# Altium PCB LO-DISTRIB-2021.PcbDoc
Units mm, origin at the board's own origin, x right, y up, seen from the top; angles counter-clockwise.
Board outline 118.3 x 92.9 mm, 2 copper layers (TopLayer, BottomLayer), stack 1.535 mm thick; 58 components, 37 nets, 177 pads, 973 vias.
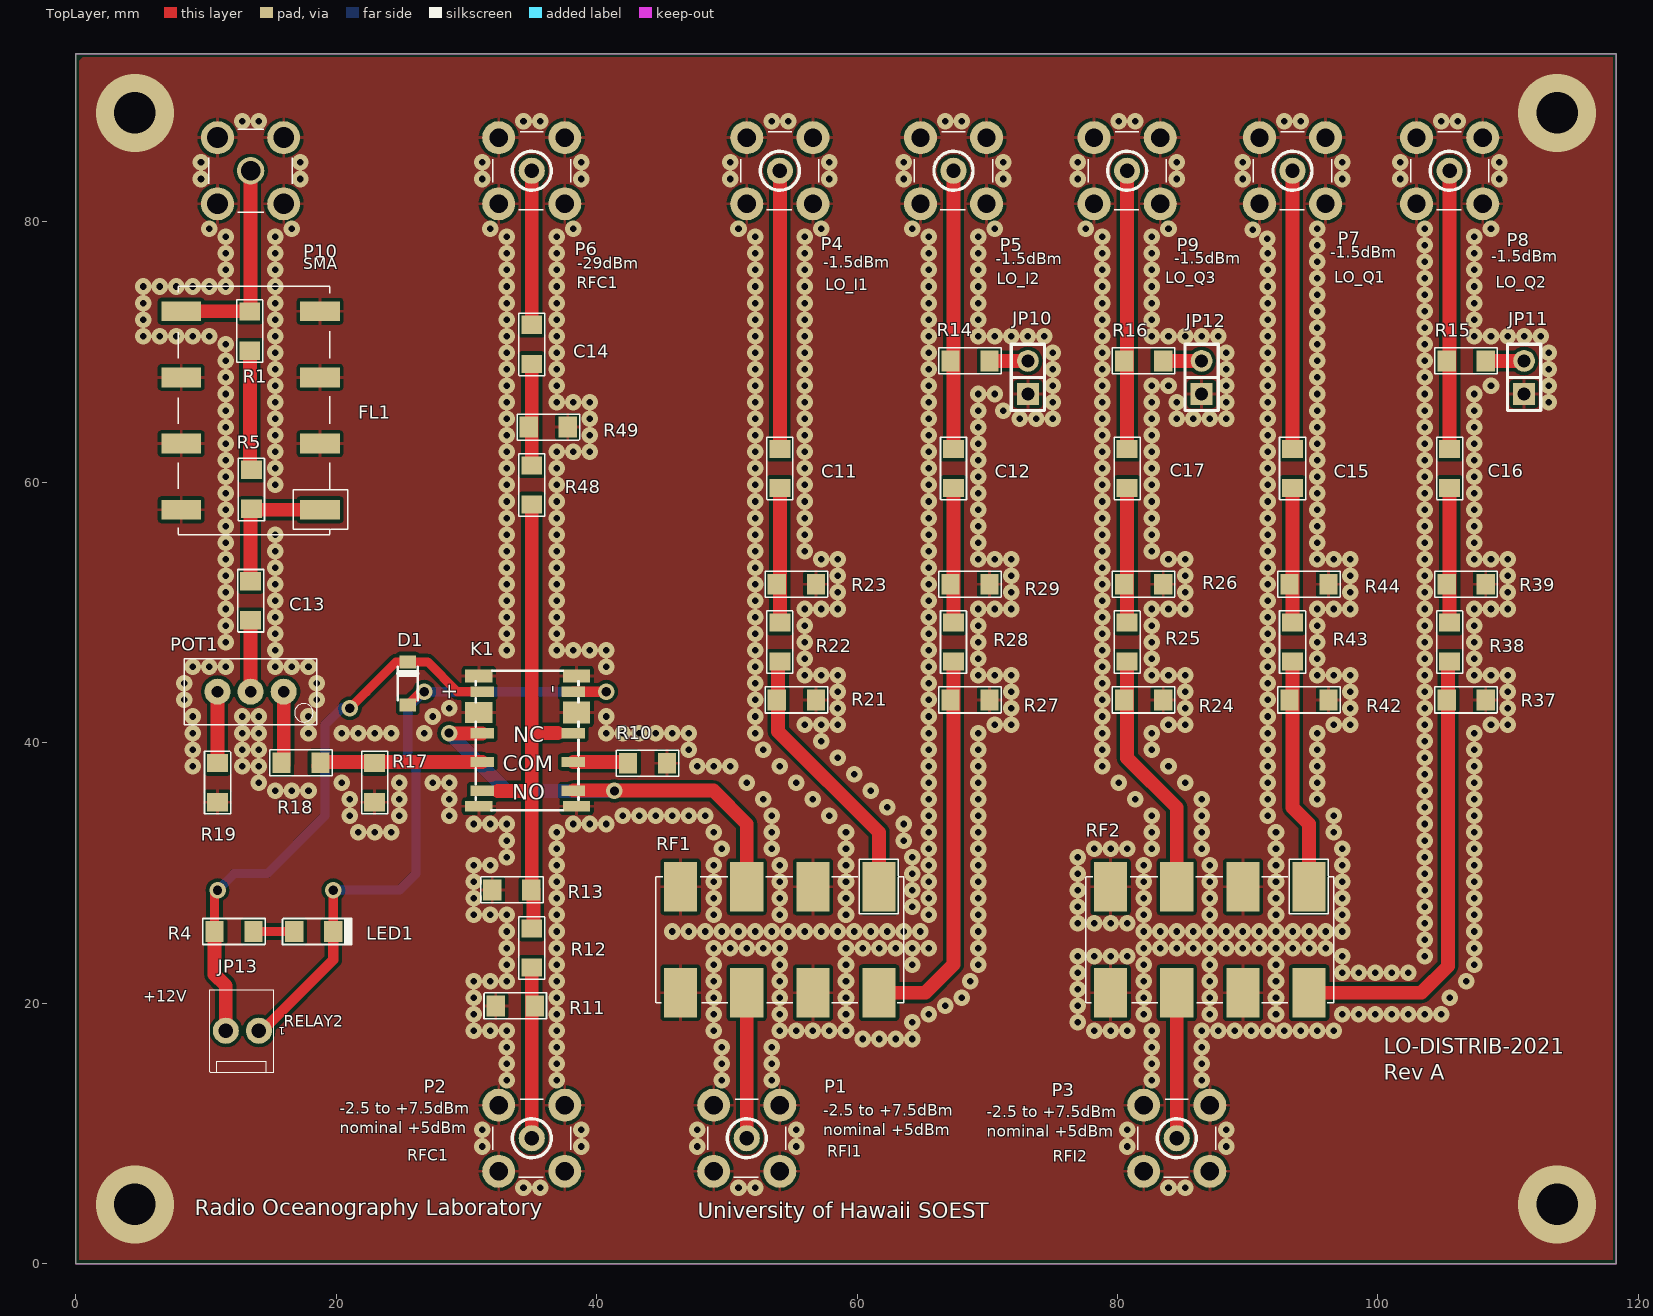
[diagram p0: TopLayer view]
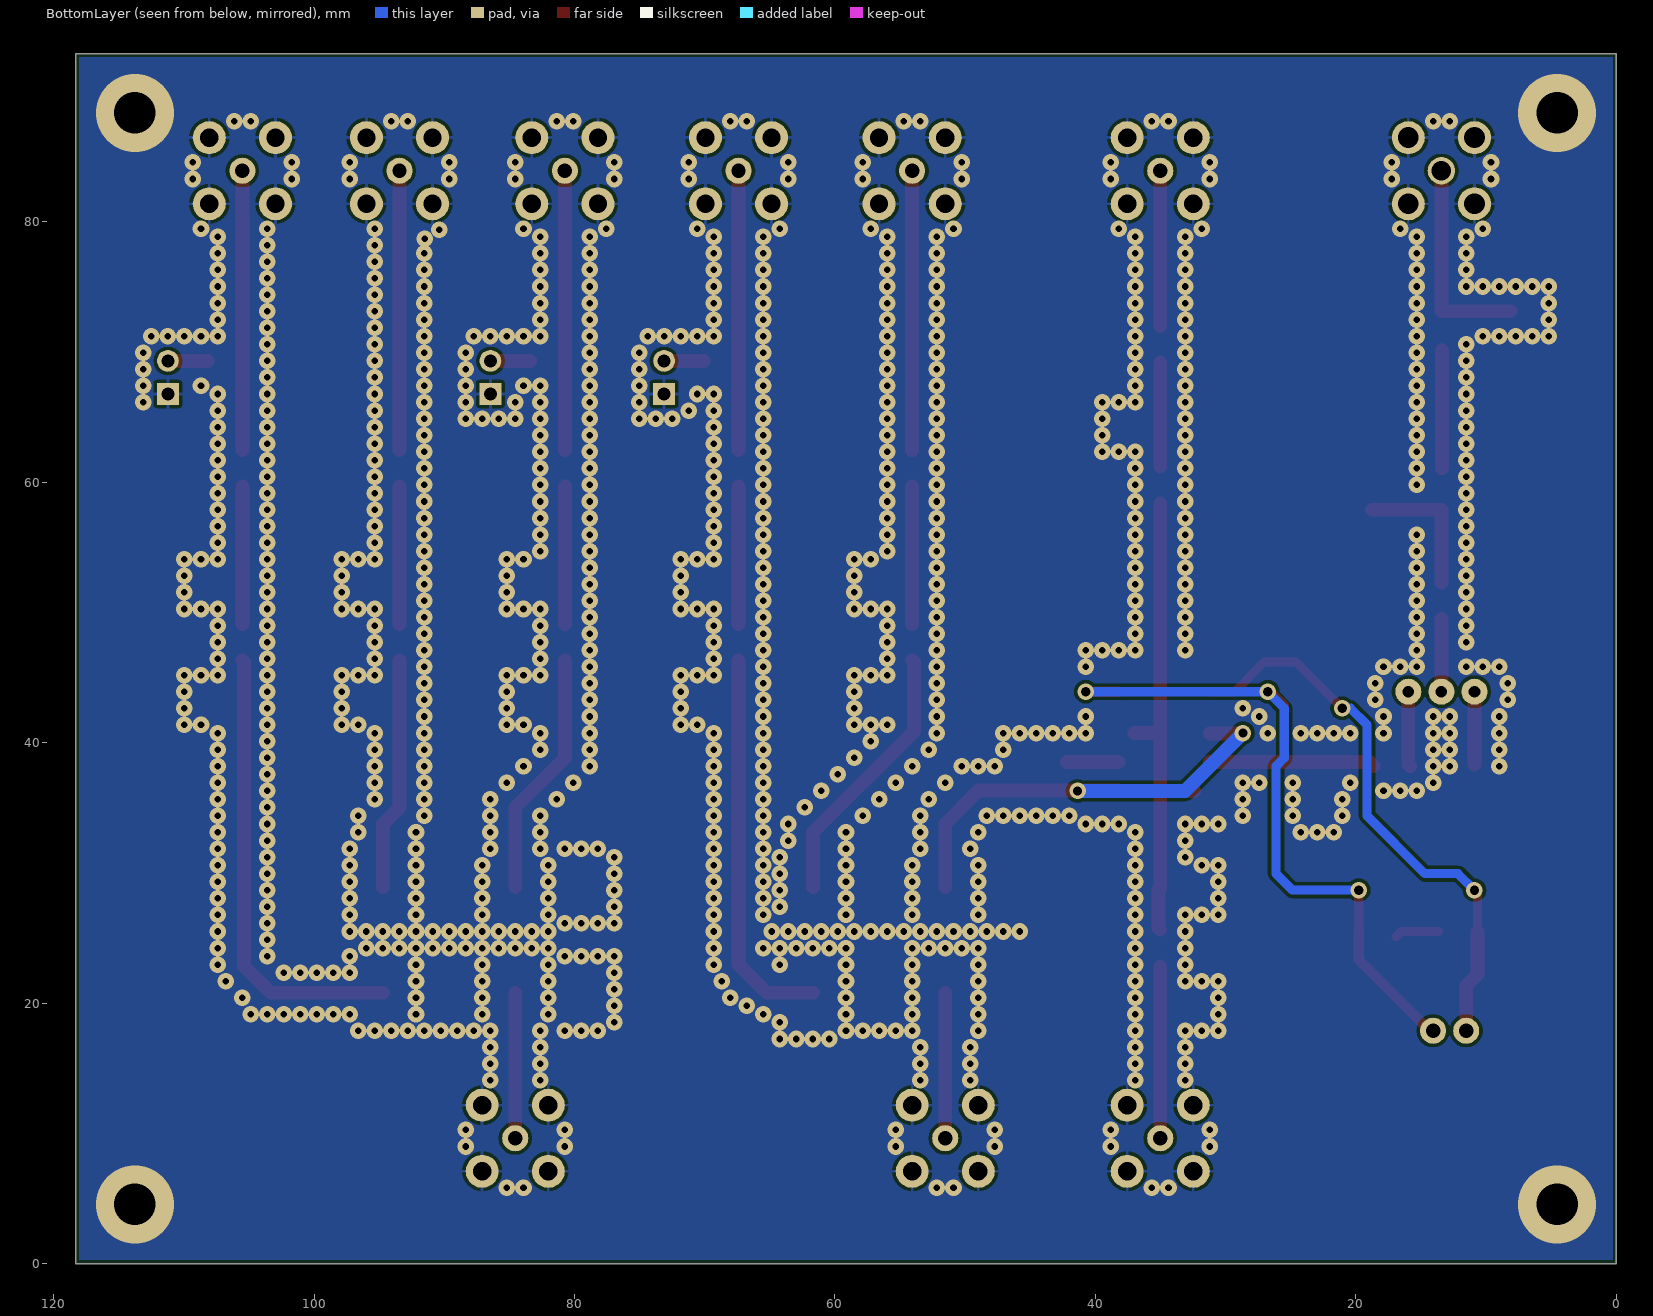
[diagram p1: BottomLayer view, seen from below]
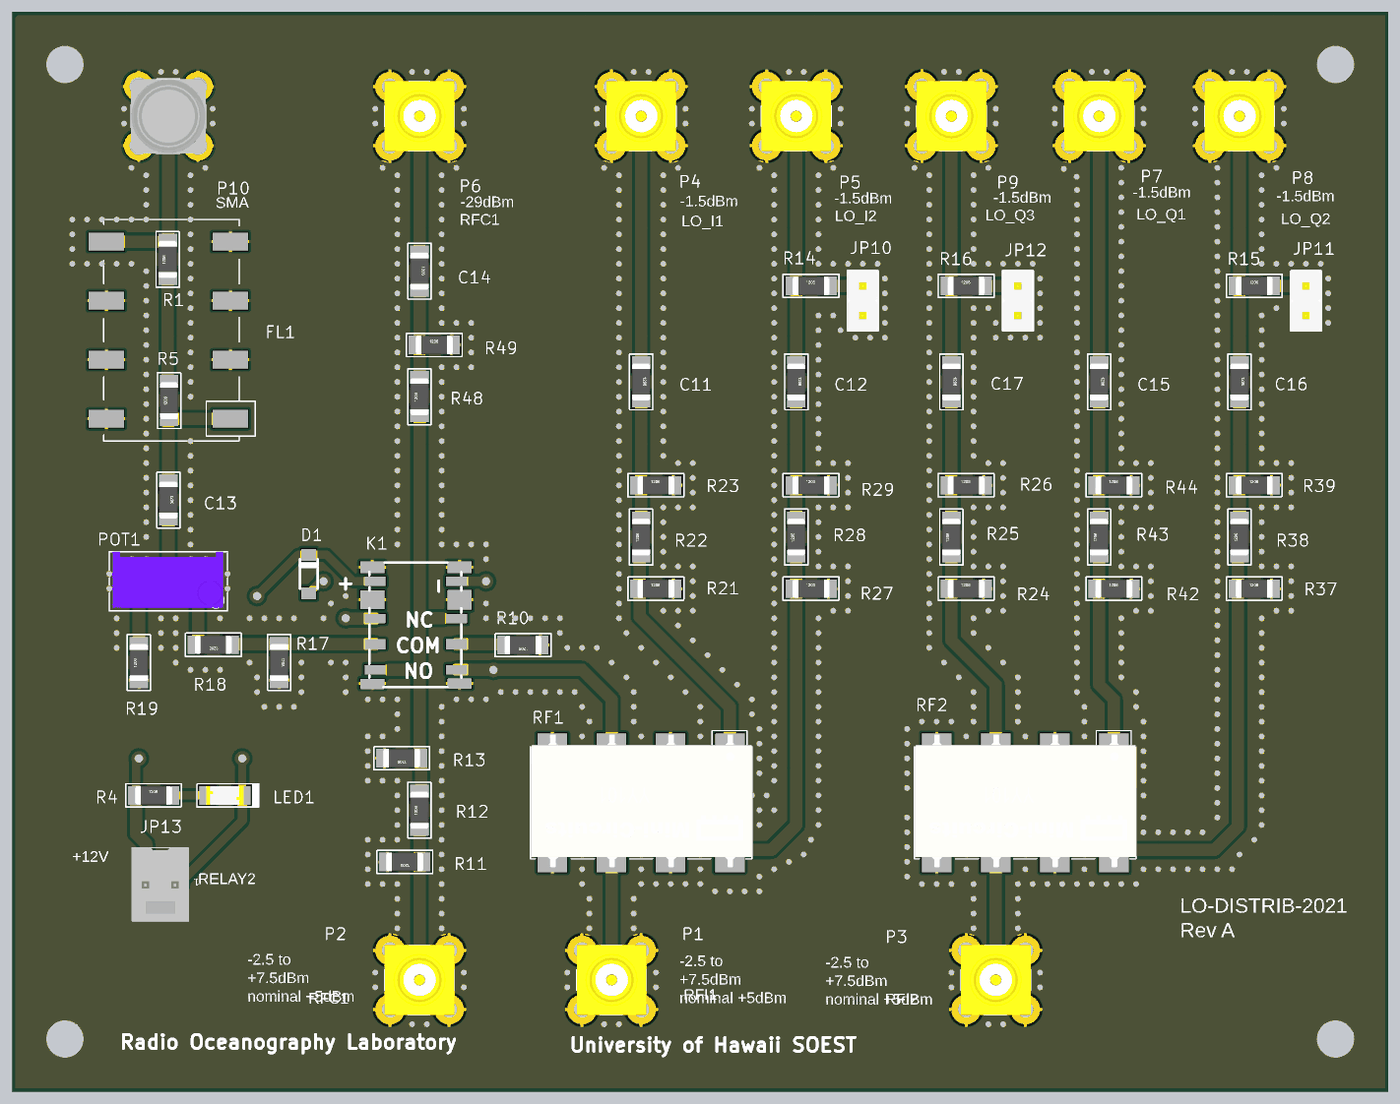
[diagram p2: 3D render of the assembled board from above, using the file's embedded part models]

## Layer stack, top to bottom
TopSolder: solder mask 0.02, Solder Resist, Dk 4
TopLayer: signal copper 0.035
Dielectric1: dielectric 1.465, FR-4, Dk 4.74
BottomLayer: signal copper 0.035
BottomSolder: solder mask 0.02, Solder Resist, Dk 4

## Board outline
0,0 118.3,0 118.3,92.9 0,92.9

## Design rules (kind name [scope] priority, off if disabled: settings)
Clearance Clearance_2 [InNetClass('50R')] p1: gap=0.257 ignorepadtopadclearanceinfootprint=FALSE except(0: Arc-Hole Track-Hole SMDPad-Hole THPad-Hole Via-Hole Fill-Hole Poly-Hole Region-Hole Text-Hole)
Clearance Clearance_1 [OnLayer('Keep-Out Layer')] p2 off: gap=0.5 ignorepadtopadclearanceinfootprint=FALSE except(0: Arc-Hole Track-Hole SMDPad-Hole THPad-Hole Via-Hole Fill-Hole Poly-Hole Region-Hole Text-Hole)
Clearance [All] p3: gap=0.257 ignorepadtopadclearanceinfootprint=FALSE except(0: Arc-Hole Track-Hole SMDPad-Hole THPad-Hole Via-Hole Fill-Hole Poly-Hole Region-Hole Text-Hole)
HoleSize [All] p1: absolutevalues=TRUE maxlimit=10 minlimit=0.025 maxpercent=80.000 minpercent=20.000
MinimumSolderMaskSliver [All] p1 off: minsoldermaskwidth=0.254
PolygonConnect [All] p1: thpad.connectstyle=Relief thpad.reliefconductorwidth=0.254 thpad.reliefentries=4 thpad.polygonreliefangle="90 Angle" thpad.airgapwidth=0.254 smdpad.connectstyle=Relief smdpad.reliefconductorwidth=0.254 smdpad.reliefentries=4 smdpad.polygonreliefangle="90 Angle" smdpad.airgapwidth=0.254 via.connectstyle=Direct via.reliefconductorwidth=0.254 via.reliefentries=4 via.polygonreliefangle="45 Angle" via.airgapwidth=0.254
RoutingVias [All] p1: holewidth=0.711 width=1.27 viastyle="Through Hole" minholewidth=0.5 minwidth=1.27 maxholewidth=0.711 maxwidth=1.27
SilkToSilkClearance [All] p1 off: silktosilkclearance=0.254
SilkToSolderMaskClearance [IsPad] p1 off: minsilkscreentomaskgap=0.254 clearancetoexposedcopper=TRUE
SolderMaskExpansion [All] p1: expansion=0.102
Width Width_1 [InNetClass('50R')] p1: maxlimit=1.064 minlimit=1.064 preferedwidth=1.064 minimp=50.000000 maximp=50.000000 favimp=50.000000
Width [All] p2: maxlimit=1.064 minlimit=0.7 preferedwidth=1.064 minimp=50.000000 maximp=50.000000 favimp=50.000000
26 further rules are at their usual default settings.

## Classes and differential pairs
net class 50R: LOI3 NetC11_1 NetC11_2 NetC12_1 NetC12_2 NetC13_1 NetC13_2 NetC14_1 NetC14_2 NetC15_1 NetC15_2 NetC16_1 NetC16_2 NetC17_1 NetC17_2 NetFL1_8 NetJP10_2 NetJP11_2 NetJP12_2 NetK1_3 NetK1_4 NetK1_6 NetR1_1 NetR21_1 NetR24_1 NetR27_1 NetR37_1 NetR42_1 RFC1 RFI1 RFQ

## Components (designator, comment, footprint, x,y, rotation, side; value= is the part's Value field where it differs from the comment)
C11 "22nF" 1206 54.07,61.055 r270 top
C12 "22nF" 1206 67.405,61.055 r270 top
C13 "22nF" 1206 13.43,50.895 r270 top
C14 "22nF" 1206 35.02,70.58 r270 top
C15 "22nF" 1206 93.44,61.055 r270 top
C16 "22nF" 1206 105.505,61.055 r270 top
C17 "22nF" 1206 80.74,61.055 r270 top
D1 "BAT-48" SOD123 25.495,44.545 r90 top
FL1 "SXLP-ff" HF1149 13.43,65.5 r90 top
JP10 "" 2X2.54 73.12,66.77 r180 top
JP11 "" 2X2.54 111.22,66.77 r180 top
JP12 "" 2X2.54 86.455,66.77 r180 top
JP13 "" 22112022 14.065,17.875 r180 top
K1 "G6K-2F-RF-S DC12" RELAY-RF 31.21,43.91 r270 top
LED1 "CAL" LED1206-BLEUE 19.78,25.495 r180 top
P1 "RF-I" MCX-J-P-H-ST-TH1 51.53,9.62 r0 top
P2 "RF-CAL" MCX-J-P-H-ST-TH1 35.02,9.62 r0 top
P3 "RF-Q" MCX-J-P-H-ST-TH1 84.55,9.62 r0 top
P4 "LO-I1" MCX-J-P-H-ST-TH1 54.07,83.915 r0 top
P5 "LO-I2" MCX-J-P-H-ST-TH1 67.405,83.915 r0 top
P6 "RF CAL" MCX-J-P-H-ST-TH1 35.02,83.915 r0 top
P7 "LO-Q1" MCX-J-P-H-ST-TH1 93.44,83.915 r0 top
P8 "LO-Q2" MCX-J-P-H-ST-TH1 105.505,83.915 r0 top
P9 "LO-Q3" MCX-J-P-H-ST-TH1 80.74,83.915 r0 top
P10 "" 5-1814832-1 13.43,83.915 r90 top
POT1 "100 POT" 3296W 10.89,43.91 r90 top
R1 "ZEROHM" 1206 13.369,71.599 r90 top
R4 "4.99K" 1206 12.16,25.495 r0 top
R5 "ZEROHM" 1206 13.495,59.451 r90 top
R10 "49.9" 1206 43.914,38.419 r180 top
R11 "178" 1206 33.75,19.78 r180 top
R12 "31.6" 1206 35.02,24.225 r90 top
R13 "178" 1206 33.489,28.692 r180 top
R14 "49.9k" 1206 68.675,69.31 r0 top
R15 "49.9k" 1206 106.775,69.31 r0 top
R16 "49.9k" 1206 82.01,69.31 r0 top
R17 "750" 1206 22.955,36.925 r270 top
R18 "10R" 1206 17.297,38.451 r180 top
R19 "49.9" 1206 10.89,36.925 r90 top
R21 "576" 1206 55.34,43.275 r0 top
R22 "8.66" 1206 54.07,47.72 r90 top
R23 "576" 1206 55.34,52.165 r0 top
R24 "576" 1206 82.01,43.275 r0 top
R25 "8.66" 1206 80.74,47.72 r90 top
R26 "576" 1206 82.01,52.165 r0 top
R27 "576" 1206 68.675,43.275 r0 top
R28 "8.66" 1206 67.405,47.72 r90 top
R29 "576" 1206 68.675,52.165 r0 top
R37 "576" 1206 106.775,43.275 r0 top
R38 "8.66" 1206 105.505,47.72 r90 top
R39 "576" 1206 106.775,52.165 r0 top
R42 "576" 1206 94.71,43.275 r0 top
R43 "8.66" 1206 93.44,47.72 r90 top
R44 "576" 1206 94.71,52.165 r0 top
R48 "9.53K" 1206 35.02,59.785 r90 top
R49 "49.9" 1206 36.29,64.23 r0 top
RF1 "SCP-3-1" SCP-3-1 54.07,24.86 r180 top
RF2 "SCP-3-1" SCP-3-1 87.09,24.86 r180 top

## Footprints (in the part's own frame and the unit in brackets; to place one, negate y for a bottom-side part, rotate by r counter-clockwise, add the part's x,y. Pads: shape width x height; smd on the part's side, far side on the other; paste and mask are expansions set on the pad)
2X2.54 [mm]
  rect 1.67x1.67 hole 1: 1(0,0)
  round 1.67 hole 1: 2(0,-2.54)
  silkscreen extent -1.27,-3.81 1.27,1.27, body extent -1.26,-3.8 1.28,1.28, height 9.54
5-1814832-1 [mm]
  round 2.1 hole 1.5: 1(0,0)
  round 2.54 hole 1.6: 2(-2.54,2.54) 5(-2.54,-2.54)
  round 2.54 hole 1.6 mask+0.1: 3(2.54,2.54) 4(2.54,-2.54)
  silkscreen extent -3.2,-3.2 3.2,3.2, body extent -3.2,-3.2 3.2,3.2, height 9.5
1206 [mm]
  rect 1.4x1.6 smd mask+0.05: 1(-1.5,0) 2(1.5,0)
  silkscreen extent -2.4,-1 2.4,1, body extent -1.6,-0.8 1.6,0.8, height 1
3296W [mm]
  round 2 hole 0.9 mask+0.1: 1(0,0) 2(0,-2.54) 3(0,-5.08)
  silkscreen extent -2.54,-7.62 2.54,2.54, body extent -2.28,-7.29 2.55,2.26, height 11.6
22112022 [mm]
  round 2 hole 1.1 mask+0.1: 1(0,0) 2(2.54,0)
  silkscreen extent -1.14,-3.14 3.78,3.19, body extent -1.13,-3.16 3.79,3.19, height 10.68
HF1149 [mil]
  rect 60x120 smd mask+3.94: 1(-300,-209.84) 2(-300,209.84) 3(-100,-209.84) 4(-100,209.84) 5(100,-209.84) 6(100,209.84) 7(300,-209.84) 8(300,209.84)
  silkscreen extent -375,-294 375,219
LED1206-BLEUE [mm]
  rect 1.4x1.6 smd: A(3,0) K(0,0)
  silkscreen extent -1.41,-1 3.9,1, body extent -0.1,-0.84 3.1,0.82, height 1.8
MCX-J-P-H-ST-TH1 [mm]
  round 2 hole 1.1 mask+0.2: 1(0,0)
  round 2.54 hole 1.4 mask+0.2: 2(-2.54,2.54) 3(-2.54,-2.54) 4(2.54,2.54) 5(2.54,-2.54)
  silkscreen extent -3,-3 3,3, body extent -3,-3 3,3, height 5.81
RELAY-RF [mm]
  rect 0.8x1.8 smd: 1(0,0) 2(3.2,0) 3(5.4,0) 4(7.6,0) 5(7.6,7) 6(5.4,7) 7(3.2,7) 8(0,7)
  rect 1x2.1 smd: 10(-1.2,-0.25) 15(-1.2,7.25)
  rect 1.6x2.1 smd: 11(1.6,-0.25)
  rect 0.8x2.1 smd: 12(8.8,-0.25) 13(8.8,7.25)
  rect 1.7x2.1 smd: 14(1.6,7.25)
  silkscreen extent -1.6,-0.5 9.1,7.4
SCP-3-1 [mm]
  rect 2.54x3.81 smd mask+0.1: 1(-7.62,-4.065) 2(-7.62,4.065) 3(-2.54,-4.065) 4(-2.54,4.065) 5(2.54,-4.065) 6(2.54,4.065) 7(7.62,-4.065) 8(7.62,4.065)
  silkscreen extent -9.53,-6.2 9.53,4.82, body extent -9.56,-5.87 9.49,5.56, height 5.34
SOD123 [mil]
  rect 40x50 smd: A(-65,0) K(65,0)
  silkscreen extent -50,-30 50,30

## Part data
C11 C12 C14 C15 C16 C17: library part CAP1206
C13: library part CAP
D1: library part "DIODE SCHOTTKY"
FL1: library part "LP FILTER_1"
JP10 JP11 JP12 JP13: library part STRAP
K1: library part "RELAY DPDT_1"
LED1: library part LED_1
P1 P2 P3: library part MCX_PCB, "MCX-J-P-H-ST-TH1"
P4 P5 P6 P7 P8 P9: library part MCX_PCB
P10: library part SMA-4G
POT1: library part POT
R1 R4 R5 R10 R17 R18 R19 R48 R49: library part RES1206
R11 R12 R13 R14 R15 R16 R21 R22 R23 R24 R25 R26 R27 R28 R29 R37 R38 R39 R42 R43 R44: library part RES

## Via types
v1: diameter 1.27, hole 0.5, TopLayer to BottomLayer, 962 vias
v2: diameter 1.27, hole 0.711, TopLayer to BottomLayer, 7 vias
v3: diameter 6, hole 3.2, TopLayer to BottomLayer, 4 vias

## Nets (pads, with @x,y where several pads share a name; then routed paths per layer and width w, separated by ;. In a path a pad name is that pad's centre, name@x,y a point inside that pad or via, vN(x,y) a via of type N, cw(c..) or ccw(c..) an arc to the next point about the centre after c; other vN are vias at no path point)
+12V: D1.K JP13.2 K1.1 R4.1 | length 43.9
  TopLayer w0.7: R4.1 10.66,28.44 v2(10.89,28.67) ; v2(21.05,42.64) 22.32,43.91 24.606,46.196 D1.K 27.019,46.196 29.305,43.91 K1.1
  TopLayer w1.064: R4.1 10.66,22.194 11.525,21.329 JP13.2
  BottomLayer w0.7: v2(10.89,28.67) 12.16,29.94 14.7,29.94 19.145,34.385 19.145,41.37 20.415,42.64 v2(21.05,42.64)
GND: FL1.2 FL1.3 FL1.4 FL1.5 FL1.6 FL1.7 JP10.1 JP11.1 JP12.1 K1.10 K1.11 K1.12 K1.13 K1.14 K1.15 P1.2 P1.3 P1.4 P1.5 P2.2 P2.3 P2.4 P2.5 P3.2 P3.3 P3.4 P3.5 P4.2 P4.3 P4.4 P4.5 P5.2 P5.3 P5.4 P5.5 P6.2 P6.3 P6.4 P6.5 P7.2 P7.3 P7.4 P7.5 P8.2 P8.3 P8.4 P8.5 P9.2 P9.3 P9.4 P9.5 P10.2 P10.3 P10.4 P10.5 R10.1 R11.2 R13.2 R17.2 R19.1 R21.2 R23.2 R24.2 R26.2 R27.2 R29.2 R37.2 R39.2 R42.2 R44.2 R49.2 RF1.3 RF1.4 RF1.7 RF1.8 RF2.3 RF2.4 RF2.7 RF2.8
  other v1: 34.385,5.81 35.655,5.81 50.895,5.81 52.165,5.81 83.915,5.81 85.185,5.81 31.21,8.985 38.83,8.985 47.72,8.985 55.34,8.985 80.74,8.985 88.36,8.985 31.21,10.255 38.83,10.255 47.72,10.255 55.34,10.255 80.74,10.255 88.36,10.255 33.115,14.065 36.925,14.065 49.625,14.065 53.435,14.065 82.645,14.065 86.455,14.065 33.115,15.335 36.925,15.335 49.625,15.335 53.435,15.335 82.645,15.335 86.455,15.335 33.115,16.605 36.925,16.605 49.625,16.605 53.435,16.605 82.645,16.605 86.455,16.605 60.42,17.24 61.69,17.24 62.96,17.24 64.23,17.24 30.575,17.875 31.845,17.875 33.115,17.875 36.925,17.875 48.99,17.875 54.07,17.875 55.34,17.875 56.61,17.875 57.88,17.875 59.15,17.875 78.2,17.875 79.47,17.875 80.74,17.875 82.645,17.875 86.455,17.875 87.725,17.875 88.995,17.875 90.265,17.875 91.535,17.875 92.805,17.875 94.075,17.875 95.345,17.875 96.615,17.875 64.23,18.51 76.93,18.51 30.575,19.145 36.925,19.145 48.99,19.145 54.07,19.145 59.15,19.145 65.5,19.145 82.01,19.145 87.09,19.145 92.17,19.145 97.25,19.145 98.52,19.145 99.79,19.145 101.06,19.145 102.33,19.145 103.6,19.145 104.87,19.145 66.77,19.78 76.93,19.78 30.575,20.415 36.925,20.415 48.99,20.415 54.07,20.415 59.15,20.415 68.04,20.415 82.01,20.415 87.09,20.415 92.17,20.415 105.505,20.415 76.93,21.05 30.575,21.685 31.845,21.685 33.115,21.685 36.925,21.685 48.99,21.685 54.07,21.685 59.15,21.685 68.675,21.685 82.01,21.685 87.09,21.685 92.17,21.685 106.775,21.685 76.93,22.32 97.25,22.32 98.52,22.32 99.79,22.32 101.06,22.32 102.33,22.32 33.115,22.955 36.925,22.955 48.99,22.955 54.07,22.955 59.15,22.955 64.23,22.955 69.31,22.955 82.01,22.955 87.09,22.955 92.17,22.955 107.41,22.955 76.93,23.59 78.2,23.59 79.47,23.59 80.74,23.59 97.25,23.59 103.6,23.59 33.115,24.225 36.925,24.225 48.99,24.225 50.26,24.225 51.53,24.225 52.8,24.225 54.07,24.225 59.15,24.225 60.42,24.225 61.69,24.225 62.96,24.225 64.23,24.225 65.5,24.225 69.31,24.225 82.01,24.225 83.28,24.225 84.55,24.225 85.82,24.225 87.09,24.225 88.36,24.225 89.63,24.225 90.9,24.225 92.17,24.225 93.44,24.225 94.71,24.225 95.98,24.225 107.41,24.225 103.6,24.86 33.115,25.495 36.925,25.495 45.815,25.495 47.085,25.495 48.355,25.495 49.625,25.495 50.895,25.495 52.165,25.495 53.435,25.495 54.705,25.495 55.975,25.495 57.245,25.495 58.515,25.495 59.785,25.495 61.055,25.495 62.325,25.495 63.595,25.495 64.865,25.495 69.31,25.495 82.01,25.495 83.28,25.495 84.55,25.495 85.82,25.495 87.09,25.495 88.36,25.495 89.63,25.495 90.9,25.495 92.17,25.495 93.44,25.495 94.71,25.495 95.98,25.495 97.25,25.495 107.41,25.495 76.93,26.13 78.2,26.13 79.47,26.13 80.74,26.13 103.6,26.13 30.575,26.765 31.845,26.765 33.115,26.765 36.925,26.765 48.99,26.765 54.07,26.765 59.15,26.765 65.5,26.765 69.31,26.765 82.01,26.765 87.09,26.765 92.17,26.765 97.25,26.765 107.41,26.765 64.23,27.4 76.93,27.4 103.6,27.4 30.575,28.035 36.925,28.035 48.99,28.035 54.07,28.035 59.15,28.035 65.5,28.035 69.31,28.035 82.01,28.035 87.09,28.035 92.17,28.035 97.25,28.035 107.41,28.035 64.23,28.67 76.93,28.67 103.6,28.67 30.575,29.305 36.925,29.305 48.99,29.305 54.07,29.305 59.15,29.305 65.5,29.305 69.31,29.305 82.01,29.305 87.09,29.305 92.17,29.305 97.25,29.305 107.41,29.305 64.23,29.94 76.93,29.94 103.6,29.94 30.575,30.575 31.845,30.575 36.925,30.575 48.99,30.575 54.07,30.575 59.15,30.575 65.5,30.575 69.31,30.575 82.01,30.575 87.09,30.575 92.17,30.575 97.25,30.575 107.41,30.575 33.115,31.21 64.23,31.21 76.93,31.21 103.6,31.21 36.925,31.845 49.625,31.845 53.435,31.845 59.15,31.845 65.5,31.845 69.31,31.845 78.2,31.845 79.47,31.845 80.74,31.845 82.645,31.845 86.455,31.845 92.17,31.845 97.25,31.845 107.41,31.845 33.115,32.48 63.595,32.48 103.6,32.48 21.685,33.115 22.955,33.115 24.225,33.115 36.925,33.115 48.99,33.115 53.435,33.115 59.15,33.115 65.5,33.115 69.31,33.115 82.645,33.115 86.455,33.115 92.17,33.115 96.615,33.115 107.41,33.115 30.575,33.75 31.845,33.75 33.115,33.75 38.195,33.75 39.465,33.75 40.735,33.75 63.595,33.75 103.6,33.75 21.05,34.385 24.86,34.385 28.67,34.385 42.005,34.385 43.275,34.385 44.545,34.385 45.815,34.385 47.085,34.385 48.355,34.385 53.435,34.385 57.88,34.385 65.5,34.385 69.31,34.385 82.645,34.385 86.455,34.385 91.535,34.385 96.615,34.385 107.41,34.385 62.325,35.02 103.6,35.02 21.05,35.655 24.86,35.655 28.67,35.655 52.8,35.655 56.61,35.655 65.5,35.655 69.31,35.655 81.375,35.655 86.455,35.655 91.535,35.655 95.345,35.655 107.41,35.655 15.335,36.29 16.605,36.29 17.875,36.29 61.055,36.29 103.6,36.29 14.065,36.925 20.415,36.925 24.86,36.925 27.4,36.925 28.67,36.925 51.53,36.925 55.34,36.925 65.5,36.925 69.31,36.925 80.105,36.925 85.185,36.925 91.535,36.925 95.345,36.925 107.41,36.925 59.785,37.56 103.6,37.56 8.985,38.195 12.795,38.195 14.065,38.195 47.72,38.195 48.99,38.195 50.26,38.195 54.07,38.195 65.5,38.195 69.31,38.195 78.835,38.195 83.915,38.195 91.535,38.195 95.345,38.195 107.41,38.195 58.515,38.83 103.6,38.83 8.985,39.465 12.795,39.465 14.065,39.465 47.085,39.465 52.8,39.465 65.5,39.465 69.31,39.465 78.835,39.465 82.645,39.465 91.535,39.465 95.345,39.465 107.41,39.465 57.245,40.1 103.6,40.1 8.985,40.735 12.795,40.735 14.065,40.735 17.875,40.735 20.415,40.735 21.685,40.735 22.955,40.735 24.225,40.735 26.765,40.735 40.735,40.735 42.005,40.735 43.275,40.735 44.545,40.735 45.815,40.735 47.085,40.735 52.165,40.735 65.5,40.735 69.31,40.735 78.835,40.735 82.645,40.735 91.535,40.735 95.345,40.735 107.41,40.735 55.975,41.37 57.245,41.37 58.515,41.37 70.58,41.37 71.85,41.37 83.915,41.37 85.185,41.37 96.615,41.37 97.885,41.37 103.6,41.37 108.68,41.37 109.95,41.37 8.985,42.005 12.795,42.005 14.065,42.005 17.875,42.005 27.4,42.005 40.735,42.005 52.165,42.005 65.5,42.005 78.835,42.005 91.535,42.005 28.67,42.64 58.515,42.64 71.85,42.64 85.185,42.64 97.885,42.64 103.6,42.64 109.95,42.64 8.35,43.275 18.51,43.275 52.165,43.275 65.5,43.275 78.835,43.275 91.535,43.275 58.515,43.91 71.85,43.91 85.185,43.91 97.885,43.91 103.6,43.91 109.95,43.91 8.35,44.545 18.51,44.545 52.165,44.545 65.5,44.545 78.835,44.545 91.535,44.545 55.975,45.18 57.245,45.18 58.515,45.18 69.31,45.18 70.58,45.18 71.85,45.18 82.645,45.18 83.915,45.18 85.185,45.18 95.345,45.18 96.615,45.18 97.885,45.18 103.6,45.18 107.41,45.18 108.68,45.18 109.95,45.18 8.985,45.815 10.255,45.815 11.525,45.815 15.335,45.815 16.605,45.815 17.875,45.815 40.735,45.815 52.165,45.815 65.5,45.815 78.835,45.815 91.535,45.815 55.975,46.45 69.31,46.45 82.645,46.45 95.345,46.45 103.6,46.45 107.41,46.45 15.335,47.085 33.115,47.085 36.925,47.085 38.195,47.085 39.465,47.085 40.735,47.085 52.165,47.085 65.5,47.085 78.835,47.085 91.535,47.085 11.525,47.72 55.975,47.72 69.31,47.72 82.645,47.72 95.345,47.72 103.6,47.72 107.41,47.72 15.335,48.355 33.115,48.355 36.925,48.355 52.165,48.355 65.5,48.355 78.835,48.355 91.535,48.355 11.525,48.99 55.975,48.99 69.31,48.99 82.645,48.99 95.345,48.99 103.6,48.99 107.41,48.99 15.335,49.625 33.115,49.625 36.925,49.625 52.165,49.625 65.5,49.625 78.835,49.625 91.535,49.625 11.525,50.26 55.975,50.26 57.245,50.26 58.515,50.26 69.31,50.26 70.58,50.26 71.85,50.26 82.645,50.26 83.915,50.26 85.185,50.26 95.345,50.26 96.615,50.26 97.885,50.26 103.6,50.26 107.41,50.26 108.68,50.26 109.95,50.26 15.335,50.895 33.115,50.895 36.925,50.895 52.165,50.895 65.5,50.895 78.835,50.895 91.535,50.895 11.525,51.53 58.515,51.53 71.85,51.53 85.185,51.53 97.885,51.53 103.6,51.53 109.95,51.53 15.335,52.165 33.115,52.165 36.925,52.165 52.165,52.165 65.5,52.165 78.835,52.165 91.535,52.165 11.525,52.8 58.515,52.8 71.85,52.8 85.185,52.8 97.885,52.8 103.6,52.8 109.95,52.8 15.335,53.435 33.115,53.435 36.925,53.435 52.165,53.435 65.5,53.435 78.835,53.435 91.535,53.435 11.525,54.07 57.245,54.07 58.515,54.07 69.31,54.07 70.58,54.07 71.85,54.07 83.915,54.07 85.185,54.07 95.345,54.07 96.615,54.07 97.885,54.07 103.6,54.07 107.41,54.07 108.68,54.07 109.95,54.07 15.335,54.705 33.115,54.705 36.925,54.705 52.165,54.705 55.975,54.705 65.5,54.705 78.835,54.705 82.645,54.705 91.535,54.705 11.525,55.34 69.31,55.34 95.345,55.34 103.6,55.34 107.41,55.34 15.335,55.975 33.115,55.975 36.925,55.975 52.165,55.975 55.975,55.975 65.5,55.975 78.835,55.975 82.645,55.975 91.535,55.975 11.525,56.61 69.31,56.61 95.345,56.61 103.6,56.61 107.41,56.61 33.115,57.245 36.925,57.245 52.165,57.245 55.975,57.245 65.5,57.245 78.835,57.245 82.645,57.245 91.535,57.245 11.525,57.88 69.31,57.88 95.345,57.88 103.6,57.88 107.41,57.88 33.115,58.515 36.925,58.515 52.165,58.515 55.975,58.515 65.5,58.515 78.835,58.515 82.645,58.515 91.535,58.515 11.525,59.15 69.31,59.15 95.345,59.15 103.6,59.15 107.41,59.15 15.335,59.785 33.115,59.785 36.925,59.785 52.165,59.785 55.975,59.785 65.5,59.785 78.835,59.785 82.645,59.785 91.535,59.785 11.525,60.42 69.31,60.42 95.345,60.42 103.6,60.42 107.41,60.42 15.335,61.055 33.115,61.055 36.925,61.055 52.165,61.055 55.975,61.055 65.5,61.055 78.835,61.055 82.645,61.055 91.535,61.055 11.525,61.69 69.31,61.69 95.345,61.69 103.6,61.69 107.41,61.69 15.335,62.325 33.115,62.325 36.925,62.325 38.195,62.325 39.465,62.325 52.165,62.325 55.975,62.325 65.5,62.325 78.835,62.325 82.645,62.325 91.535,62.325 11.525,62.96 69.31,62.96 95.345,62.96 103.6,62.96 107.41,62.96 15.335,63.595 33.115,63.595 39.465,63.595 52.165,63.595 55.975,63.595 65.5,63.595 78.835,63.595 82.645,63.595 91.535,63.595 11.525,64.23 69.31,64.23 95.345,64.23 103.6,64.23 107.41,64.23 15.335,64.865 33.115,64.865 39.465,64.865 52.165,64.865 55.975,64.865 65.5,64.865 72.485,64.865 73.755,64.865 75.025,64.865 78.835,64.865 82.645,64.865 84.55,64.865 85.82,64.865 87.09,64.865 88.36,64.865 91.535,64.865 11.525,65.5 69.31,65.5 71.215,65.5 95.345,65.5 103.6,65.5 107.41,65.5 15.335,66.135 33.115,66.135 36.925,66.135 38.195,66.135 39.465,66.135 52.165,66.135 55.975,66.135 65.5,66.135 75.025,66.135 78.835,66.135 82.645,66.135 84.55,66.135 88.36,66.135 91.535,66.135 113.125,66.135 11.525,66.77 69.31,66.77 70.58,66.77 95.345,66.77 103.6,66.77 107.41,66.77 15.335,67.405 33.115,67.405 36.925,67.405 52.165,67.405 55.975,67.405 65.5,67.405 75.025,67.405 78.835,67.405 82.645,67.405 83.915,67.405 88.36,67.405 91.535,67.405 108.68,67.405 113.125,67.405 11.525,68.04 95.345,68.04 103.6,68.04 15.335,68.675 33.115,68.675 36.925,68.675 52.165,68.675 55.975,68.675 65.5,68.675 75.025,68.675 78.835,68.675 88.36,68.675 91.535,68.675 113.125,68.675 11.525,69.31 95.345,69.31 103.6,69.31 15.335,69.945 33.115,69.945 36.925,69.945 52.165,69.945 55.975,69.945 65.5,69.945 75.025,69.945 78.835,69.945 88.36,69.945 91.535,69.945 113.125,69.945 11.525,70.58 95.345,70.58 103.6,70.58 5.175,71.215 6.445,71.215 7.715,71.215 8.985,71.215 10.255,71.215 15.335,71.215 33.115,71.215 36.925,71.215 52.165,71.215 55.975,71.215 65.5,71.215 69.31,71.215 70.58,71.215 71.85,71.215 73.12,71.215 74.39,71.215 78.835,71.215 82.645,71.215 83.915,71.215 85.185,71.215 86.455,71.215 87.725,71.215 91.535,71.215 107.41,71.215 108.68,71.215 109.95,71.215 111.22,71.215 112.49,71.215 95.345,71.85 103.6,71.85 5.175,72.485 15.335,72.485 33.115,72.485 36.925,72.485 52.165,72.485 55.975,72.485 65.5,72.485 69.31,72.485 78.835,72.485 82.645,72.485 91.535,72.485 107.41,72.485 95.345,73.12 103.6,73.12 5.175,73.755 15.335,73.755 33.115,73.755 36.925,73.755 52.165,73.755 55.975,73.755 65.5,73.755 69.31,73.755 78.835,73.755 82.645,73.755 91.535,73.755 107.41,73.755 95.345,74.39 103.6,74.39 5.175,75.025 6.445,75.025 7.715,75.025 8.985,75.025 10.255,75.025 11.525,75.025 15.335,75.025 33.115,75.025 36.925,75.025 52.165,75.025 55.975,75.025 65.5,75.025 69.31,75.025 78.835,75.025 82.645,75.025 91.535,75.025 107.41,75.025 95.345,75.66 103.6,75.66 11.525,76.295 15.335,76.295 33.115,76.295 36.925,76.295 52.165,76.295 55.975,76.295 65.5,76.295 69.31,76.295 78.835,76.295 82.645,76.295 91.535,76.295 107.41,76.295 95.345,76.93 103.6,76.93 11.525,77.565 15.335,77.565 33.115,77.565 36.925,77.565 52.165,77.565 55.975,77.565 65.5,77.565 69.31,77.565 78.835,77.565 82.645,77.565 91.535,77.565 107.41,77.565 95.345,78.2 103.6,78.2 91.501,78.704 11.525,78.835 15.335,78.835 33.115,78.835 36.925,78.835 52.165,78.835 55.975,78.835 65.5,78.835 69.31,78.835 78.835,78.835 82.645,78.835 107.41,78.835 90.4,79.377 10.255,79.47 16.605,79.47 31.845,79.47 38.195,79.47 50.895,79.47 57.245,79.47 64.23,79.47 70.58,79.47 77.565,79.47 83.915,79.47 95.345,79.47 103.6,79.47 108.68,79.47 9.62,83.28 17.24,83.28 31.21,83.28 38.83,83.28 50.26,83.28 57.88,83.28 63.595,83.28 71.215,83.28 76.93,83.28 84.55,83.28 89.63,83.28 97.25,83.28 101.695,83.28 109.315,83.28 9.62,84.55 17.24,84.55 31.21,84.55 38.83,84.55 50.26,84.55 57.88,84.55 63.595,84.55 71.215,84.55 76.93,84.55 84.55,84.55 89.63,84.55 97.25,84.55 101.695,84.55 109.315,84.55 12.795,87.725 14.065,87.725 34.385,87.725 35.655,87.725 53.435,87.725 54.705,87.725 66.77,87.725 68.04,87.725 80.105,87.725 81.375,87.725 92.805,87.725 94.075,87.725 104.87,87.725 106.14,87.725
  other v3: 4.54,4.54 113.76,4.54 4.54,88.36 113.76,88.36
LOI3: K1.2 K1.5 RF1.5 | length 36.3
  TopLayer w1.064: v2(28.67,40.735) 28.695,40.71 K1.2 ; K1.5 41.35,36.31 v2(41.37,36.29) ; v2@41.37,36.31 48.97,36.31 51.53,33.75 RF1.5
  BottomLayer w1.064: v2(28.67,40.735) 33.115,36.29 v2(41.37,36.29)
NetC11_1: C11.1 P4.1 | length 21.5
  TopLayer w1.064: C11.1@54.07,62.455 P4.1
NetC11_2: C11.2 R22.2 R23.1 | length 10.5
  TopLayer w1.064: R22.2@54.07,49.12 C11.2@54.07,59.655
NetC12_1: C12.1 P5.1 R14.1 | length 21.5
  TopLayer w1.064: C12.1@67.405,62.455 P5.1
NetC12_2: C12.2 R28.2 R29.1 | length 10.5
  TopLayer w1.064: R28.2@67.405,49.12 C12.2@67.405,59.655
NetC13_1: C13.1 FL1.1 R5.1 | length 10.9
  TopLayer w1.064: C13.1@13.43,52.295 13.43,57.88 FL1.1
NetC13_2: C13.2 POT1.2 | length 5.6
  TopLayer w1.064: POT1.2 C13.2@13.43,49.495
NetC14_1: C14.1 P6.1 | length 11.9
  TopLayer w1.064: C14.1@35.02,71.98 P6.1
NetC14_2: C14.2 R48.2 R49.1 | length 8
  TopLayer w1.064: R48.2@35.02,61.185 C14.2@35.02,69.18
NetC15_1: C15.1 P7.1 | length 21.5
  TopLayer w1.064: C15.1@93.44,62.455 P7.1
NetC15_2: C15.2 R43.2 R44.1 | length 10.5
  TopLayer w1.064: R43.2@93.44,49.12 C15.2@93.44,59.655
NetC16_1: C16.1 P8.1 R15.1 | length 21.5
  TopLayer w1.064: C16.1@105.505,62.455 P8.1
NetC16_2: C16.2 R38.2 R39.1 | length 10.5
  TopLayer w1.064: R38.2@105.505,49.12 C16.2@105.505,59.655
NetC17_1: C17.1 P9.1 R16.1 | length 21.5
  TopLayer w1.064: C17.1@80.74,62.455 P9.1
NetC17_2: C17.2 R25.2 R26.1 | length 10.5
  TopLayer w1.064: R25.2@80.74,49.12 C17.2@80.74,59.655
NetFL1_8: FL1.8 P10.1 R1.2 | length 16.1
  TopLayer w1.064: FL1.8 13.43,73.12 P10.1
NetJP10_2: JP10.2 R14.2 | length 3
  TopLayer w1.064: R14.2@70.075,69.31 JP10.2
NetJP11_2: JP11.2 R15.2 | length 3
  TopLayer w1.064: R15.2@108.175,69.31 JP11.2
NetJP12_2: JP12.2 R16.2 | length 3
  TopLayer w1.064: R16.2@83.41,69.31 JP12.2
NetK1_3: K1.3 R17.1 R18.1 | length 12.7
  TopLayer w1.064: R18.1@18.64,38.195 18.955,38.51 K1.3
NetK1_4: K1.4 K1.7 R12.2 R13.1 R48.1 | length 37.5
  TopLayer w1.064: 32.405,36.29 35.02,36.29 ; R12.2@35.02,25.625 35.15,25.755 35.15,28.67 35.02,28.8 35.02,36.29 ; R48.1@35.02,58.385 35.02,40.735 ; 37.005,40.735 35.02,40.735 ; 35.02,36.29 35.02,40.735
NetK1_6: K1.6 R10.2 | length 4
  TopLayer w1.064: K1.6 R10.2@42.19,38.51
NetLED1_A: LED1.A R4.2 | length 3.4
  TopLayer w0.7: R4.2 16.501,25.495 LED1.A@16.917,25.079
NetPOT1_1: POT1.1 R19.2 | length 5.6
  TopLayer w1.064: R19.2@10.89,38.325 POT1.1
NetPOT1_3: POT1.3 R18.2 | length 5.8
  TopLayer w1.064: R18.2@15.84,38.195 15.97,38.325 POT1.3
NetR1_1: R1.1 R5.2 | length 9
  TopLayer w1.064: R5.2@13.369,61.082 R1.1
NetR21_1: R21.1 R22.1 RF1.1 | length 20.7
  TopLayer w1.064: R22.1@54.07,46.32 53.94,46.19 53.94,43.275 53.94,40.865 61.69,33.115 RF1.1
NetR24_1: R24.1 R25.1 RF2.5 | length 19
  TopLayer w1.064: R25.1@80.74,46.32 80.74,38.83 84.55,35.02 RF2.5
NetR27_1: R27.1 R28.1 RF1.2 | length 30
  TopLayer w1.064: RF1.2 65.245,20.795 67.405,22.955 R28.1@67.405,46.32
NetR37_1: R37.1 R38.1 RF2.2 | length 35.1
  TopLayer w1.064: RF2.2 103.345,20.795 105.375,22.825 105.375,43.275 105.375,46.19 R38.1@105.505,46.32
NetR42_1: R42.1 R43.1 RF2.1 | length 17.9
  TopLayer w1.064: R43.1@93.44,46.32 93.44,35.02 94.71,33.75 RF2.1
RELAY2: D1.A JP13.1 K1.8 LED1.K | length 53
  TopLayer w0.7: LED1.K v2(19.78,28.67) ; D1.A 26.511,43.91 v2(26.765,43.91)
  TopLayer w0.8: JP13.1@14.224,17.76 19.78,23.316 LED1.K ; K1.8 v2(40.735,43.91)
  BottomLayer w0.7: v2(19.78,28.67) 24.86,28.67 26.13,29.94 26.13,38.195 25.495,38.83 25.495,42.64 v2(26.765,43.91) v2(40.735,43.91)
RFC1: P2.1 R11.1 R12.1 | length 13.2
  TopLayer w1.064: P2.1 R12.1@35.02,22.825
RFI1: P1.1 RF1.6 | length 11.2
  TopLayer w1.064: P1.1 RF1.6
RFQ: P3.1 RF2.6 | length 11.2
  TopLayer w1.064: P3.1 RF2.6

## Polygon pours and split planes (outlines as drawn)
GND on BottomLayer "Bottom Layer-No Net" (solid, remove dead copper, pour order 0): -0.54,-0.1 117.3,-0.1 118.4,-0.1 118.4,93 -0.54,93
GND on TopLayer "Bottom Layer-No Net" (solid, remove dead copper, pour order 2): -0.7,-1.27 117.13,-0.1 118.3,-1.27 118.3,92.9 0.825,92.9 -1.175,90.9

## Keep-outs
Keep-Out Layer:
  the board outline again, w0.05

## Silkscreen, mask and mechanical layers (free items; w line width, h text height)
TopOverlay:
  text "-1.5dBm" at 96.323,76.918 h1.5
  text "-1.5dBm" at 108.68,76.601 h1.5
  text "-1.5dBm" at 84.345,76.475 h1.5
  text "-1.5dBm" at 70.657,76.411 h1.5
  text "-1.5dBm" at 57.412,76.158 h1.5
  text "-29dBm" at 38.527,76.095 h1.5
  text "SMA" at 17.487,76.031 h1.5
  text "LO_Q1" at 96.64,75.017 h1.5
  text "LO_Q3" at 83.648,74.954 h1.5
  text "LO_I2" at 70.72,74.89 h1.5
  text "LO_Q2" at 109.061,74.637 h1.5
  text "RFC1" at 38.464,74.574 h1.5
  text "LO_I1" at 57.539,74.447 h1.5
  text "+12V" at 5.175,19.78 h1.5
  text "RELAY2" at 15.97,17.875 h1.5
  text "LO-DISTRIB-2021 / Rev A" at 100.442,13.736 h2
  text "-2.5 to +7.5dBm / nominal +5dBm" at 20.276,9.68 h1.5
  text "-2.5 to +7.5dBm / nominal +5dBm" at 57.412,9.553 h1.5
  text "-2.5 to +7.5dBm / nominal +5dBm" at 69.96,9.426 h1.5
  text "RFI1" at 57.729,7.906 h1.5
  text "RFC1" at 25.472,7.589 h1.5
  text "RFI2" at 75.03,7.525 h1.5
  text "Radio Oceanography Laboratory" at 9.122,3.723 h1.2
  text "University of Hawaii SOEST" at 47.779,3.469 h1.2
Mechanical 5:
  lines w0.127: 81.143,-79.09 81.143,-70.409 ; 120.251,-63.584 237.554,-63.584 ; 120.251,-56.759 237.554,-56.759 ; 120.251,-45.669 237.554,-45.669 ; 120.251,-41.403 237.554,-41.403 ; 120.251,-37.137 237.554,-37.137 ; 120.251,-32.872 237.554,-32.872 ; 143.626,-49.934 143.626,-28.606 ; 161.124,-70.409 161.124,-49.934 ; 201.322,-49.934 201.322,-28.606 ; 220.345,-49.934 220.345,-28.606 ; 237.554,-28.606 81.143,-28.606 ; 81.143,-70.409 237.554,-70.409 ; 81.143,-70.409 120.251,-70.409 ; 81.143,-70.409 81.143,-28.606 ; 81.143,-28.606 120.251,-28.606 ; 120.251,-70.409 120.251,-28.606 ; 120.251,-70.409 120.251,-28.606 ; 120.251,-70.409 237.554,-70.409 ; 120.251,-70.409 120.251,-49.934 ; 120.251,-49.934 237.554,-49.934 ; 120.251,-49.934 237.554,-49.934 ; 219.486,-70.409 219.486,-56.759 ; 219.486,-70.409 237.554,-70.409 ; 219.486,-70.409 219.486,-56.759 ; 219.486,-63.584 219.486,-56.759 ; 219.486,-63.584 237.554,-63.584 ; 219.486,-63.584 219.486,-56.759 ; 219.486,-56.759 237.554,-56.759 ; 219.486,-56.759 237.554,-56.759 ; 237.554,-70.409 237.554,-56.759 ; 237.554,-70.409 237.554,-49.934 ; 237.554,-63.584 237.554,-56.759
  lines w0.5: -49.437,-79.078 81.163,-79.078 237.563,-79.078 237.563,130.922 -49.437,130.922 -49.437,-79.078
  text "Radio / Oceanography / Laboratory" at 87.09,-43.196 h4
  text "Indice" at 124.312,-48.525 h1.76
  text "Modification" at 163.281,-48.525 h1.76
  text "Date" at 206.955,-48.525 h1.76
  text "Dessine par" at 222.51,-48.607 h1.5
  text "Edition" at 121.222,-54.536 h1.76
  text ":" at 141.16,-54.536 h1.76
  text "CARTE LO-DISTRIB-2021" at 164.963,-55.178 h1.8
  text "Dessinateur" at 121.222,-60.547 h1.76
  text "Folio" at 220.361,-60.547 h1.8
  text ":" at 141.16,-60.568 h1.76
  text ":" at 228.83,-60.568 h1.76
  text "1/1" at 231.207,-60.944 h1.76
  text "RONVEL" at 144.228,-61.059 h1.95
  text ":" at 141.16,-67.161 h1.76
  text "Date" at 121.222,-67.212 h1.76
  text "Ind" at 220.361,-67.212 h1.95
  text "09/06/2021" at 143.263,-68.178 h1.8
Mechanical7:
  text "PLAN DE CABLAGE" at 168.963,-61.678 h4
Mechanical9:
  text "PLAN DE PERCAGE" at 174.563,-61.578 h4
Drill Drawing:
  drawing of 559 lines, arcs and shapes, not listed
  text "Layer" at 103.05,119.55 h1
  text "Name" at 109.749,119.55 h1
  text "Material" at 124.111,119.55 h1
  text "Thickness" at 138.307,119.55 h1
  text "Constant" at 149.005,119.55 h1
  text "Board Layer Stack" at 158.369,119.55 h1
  text "Board Layer Stack" at 176.897,119.55 h1
  text "Board Layer Stack" at 195.425,119.55 h1
  text "Board Layer Stack" at 213.953,119.55 h1
  text "1" at 103.05,117.55 h1
  text "TopOverlay" at 109.749,117.55 h1
  text "2" at 103.05,115.55 h1
  text "TopSolder" at 109.749,115.55 h1
  text "Solder Resist" at 124.111,115.55 h1
  text "0,020mm" at 138.307,115.55 h1
  text "4" at 149.005,115.55 h1
  text "3" at 103.05,113.55 h1
  text "TopLayer" at 109.749,113.55 h1
  text "Copper" at 124.111,113.55 h1
  text "0,035mm" at 138.307,113.55 h1
  text "4" at 103.05,111.55 h1
  text "Dielectric1" at 109.749,111.55 h1
  text "FR-4" at 124.111,111.55 h1
  text "1,465mm" at 138.307,111.55 h1
  text "4,74" at 149.005,111.55 h1
  text "5" at 103.05,109.55 h1
  text "BottomLayer" at 109.749,109.55 h1
  text "Copper" at 124.111,109.55 h1
  text "0,035mm" at 138.307,109.55 h1
  text "6" at 103.05,107.55 h1
  text "BottomSolder" at 109.749,107.55 h1
  text "Solder Resist" at 124.111,107.55 h1
  text "0,020mm" at 138.307,107.55 h1
  text "4" at 149.005,107.55 h1
  text "7" at 103.05,105.55 h1
  text "BottomOverlay" at 109.749,105.55 h1
  text "Symbol" at 128.55,91.8 h1.2
  text "Count" at 136.768,91.8 h1.2
  text "Hole Size" at 147.465,91.8 h1.2
  text "Plated" at 166.826,91.8 h1.2
  text "Hole Type" at 175.044,91.8 h1.2
  text "Drill Layer Pair" at 187.061,91.8 h1.2
  text "Via/Pad" at 209.92,91.8 h1.2
  text "Pad Shape" at 219.538,91.8 h1.2
  text "1" at 136.768,89.3 h1
  text "1,500mm (59,06mil)" at 147.465,89.3 h1
  text "PTH" at 166.826,89.3 h1
  text "Round" at 175.044,89.3 h1
  text "TopLayer - BottomLayer" at 187.061,89.3 h1
  text "Pad" at 209.92,89.3 h1
  text "Rounded" at 219.538,89.3 h1
  text "3" at 136.768,86.8 h1
  text "0,900mm (35,43mil)" at 147.465,86.8 h1
  text "PTH" at 166.826,86.8 h1
  text "Round" at 175.044,86.8 h1
  text "TopLayer - BottomLayer" at 187.061,86.8 h1
  text "Pad" at 209.92,86.8 h1
  text "Rounded" at 219.538,86.8 h1
  text "4" at 136.768,84.3 h1
  text "1,600mm (62,99mil)" at 147.465,84.3 h1
  text "PTH" at 166.826,84.3 h1
  text "Round" at 175.044,84.3 h1
  text "TopLayer - BottomLayer" at 187.061,84.3 h1
  text "Pad" at 209.92,84.3 h1
  text "Rounded" at 219.538,84.3 h1
  text "4" at 136.768,81.8 h1
  text "3,200mm (125,98mil)" at 147.465,81.8 h1
  text "PTH" at 166.826,81.8 h1
  text "Round" at 175.044,81.8 h1
  text "TopLayer - BottomLayer" at 187.061,81.8 h1
  text "Via" at 209.92,81.8 h1
  text "Rounded" at 219.538,81.8 h1
  text "6" at 136.768,79.3 h1
  text "1,000mm (39,37mil)" at 147.465,79.3 h1
  text "PTH" at 166.826,79.3 h1
  text "Round" at 175.044,79.3 h1
  text "TopLayer - BottomLayer" at 187.061,79.3 h1
  text "Pad" at 209.92,79.3 h1
  text "(Mixed)" at 219.538,79.3 h1
  text "7" at 136.768,76.8 h1
  text "0,711mm (28,00mil)" at 147.465,76.8 h1
  text "PTH" at 166.826,76.8 h1
  text "Round" at 175.044,76.8 h1
  text "TopLayer - BottomLayer" at 187.061,76.8 h1
  text "Via" at 209.92,76.8 h1
  text "Rounded" at 219.538,76.8 h1
  text "11" at 136.768,74.3 h1
  text "1,100mm (43,31mil)" at 147.465,74.3 h1
  text "PTH" at 166.826,74.3 h1
  text "Round" at 175.044,74.3 h1
  text "TopLayer - BottomLayer" at 187.061,74.3 h1
  text "Pad" at 209.92,74.3 h1
  text "Rounded" at 219.538,74.3 h1
  text "36" at 136.768,71.8 h1
  text "1,400mm (55,12mil)" at 147.465,71.8 h1
  text "PTH" at 166.826,71.8 h1
  text "Round" at 175.044,71.8 h1
  text "TopLayer - BottomLayer" at 187.061,71.8 h1
  text "Pad" at 209.92,71.8 h1
  text "Rounded" at 219.538,71.8 h1
  text "962" at 136.768,69.3 h1
  text "0,500mm (19,69mil)" at 147.465,69.3 h1
  text "PTH" at 166.826,69.3 h1
  text "Round" at 175.044,69.3 h1
  text "TopLayer - BottomLayer" at 187.061,69.3 h1
  text "Via" at 209.92,69.3 h1
  text "Rounded" at 219.538,69.3 h1
  text "1034 Total" at 136.768,66.8 h1
  text "MATIERE FR4 / CUIVRE (voir empilage) / SERIGRAPHIE BLANCHE FACE TOP / VERNIS VERT SELECTIF 2 FACES / FINITION NiAu /  / PISTES 50ohms largeur 1.064mm  face TOP" at 134.125,38.375 h3.5

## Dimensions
0,92.9 to 0,0 on Drill Drawing
0,92.9 to 118.3,92.9 on Drill Drawing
